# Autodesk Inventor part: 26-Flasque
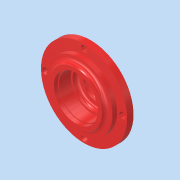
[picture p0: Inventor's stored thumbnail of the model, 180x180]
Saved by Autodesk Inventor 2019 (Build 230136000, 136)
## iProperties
Created: 2023-02
Part Number: 26-Flasque
Material: Générique
Document SubType Name: Modeling
Designer: Thier
Density: 1 g/cm^3
Appearance: Rouge clair
Author: Thier
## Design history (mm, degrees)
sketch "Esquisse1"
  geometry: L1 (47, 22)-(47, 15); L2 (47, 15)-(31.5, 15); L3 (31.5, 15)-(31.5, 0); L4 (31.5, 0)-(0, 0); L5 (0, 0)-(0, 5.797); L6 (14.5, 8.5)-(21, 8.5); L7 (21, 8.5)-(21, 13.5); L8 (21, 13.5)-(23, 13.5); L9 (23, 13.5)-(23, 26.5); L10 (23, 26.5)-(24, 26.5); L11 (24, 26.5)-(24, 31); L12 (24, 31)-(28.5, 31); L13 (28.5, 31)-(28.5, 27); L14 (28.5, 27)-(36, 27); L15 (36, 27)-(36, 22); L16 (36, 22)-(47, 22); L17 (14.5, 8.5)-(14.5, 3.5); L18 (14.5, 3.5)-(0, 3.5); 1 further point
  constraints: 36 end point, 13 perpendicular, 3 parallel, 2 vertical, 1 coincident, 1 point on line
  dimensions: "d0" = 94 diameter of L1 L5; "d1" = 72 diameter of L15 L5; "d2" = 57 diameter of L13 L5; "d3" = 48 diameter of L11 L5; "d4" = 46 diameter of L9 L5; "d5" = 42 diameter of L7 L5; "d6" = 29 diameter of L17 L5; "d7" = 7 distance of L1.start L1.end; "d8" = 5 distance of L14.end L15.end; "d9" = 4 distance of L12.end L13.end; "d10" = 31 distance between parallel lines of L4 L12; "d11" = 4.5 distance of L10.end L11.end; "d12" = 13 distance of L8.end L9.end; "d13" = 5 distance of L6.end L7.end; "d14" = 5 distance of L6.start L17.end; "d16" = 15 distance of L2.end L3.end (derived); "d17" = 63 diameter of L3 L5
revolve "Révolution1" sketch "Esquisse1" stored, may be unused: angle "d15" = 90 deg
chamfer "Chanfrein1" distance "d18" = 9; stored, may be unused: second distance "d19" = 15, angle "d20" = 45 deg
fillet "Congé1" dims "d24" = 3
fillet "Congé2" dims "d25" = 5
fillet "Congé3" dims "d26" = 3
sketch "Esquisse3"
  geometry: C1 r 47 at (0, 0) reference; 2 further points
  dimensions: "d46" = 0 vertical distance of C1.centre point (-42, 0); "d47" = 42 distance of C1.centre point (-42, 0)
hole "Perçage2" sketch "Esquisse3" at (-42, 0) diameter "d39" = 7; stored, may be unused: countersink angle "d43" = 90 deg, drill point angle "d45" = 118 deg; dims "d40" = 6, "d41" = 4, "d42" = 2, "d44" = 8
pattern_circular "Réseau circulaire2" dims angle "d49" = 360 deg
node "Solide1"
